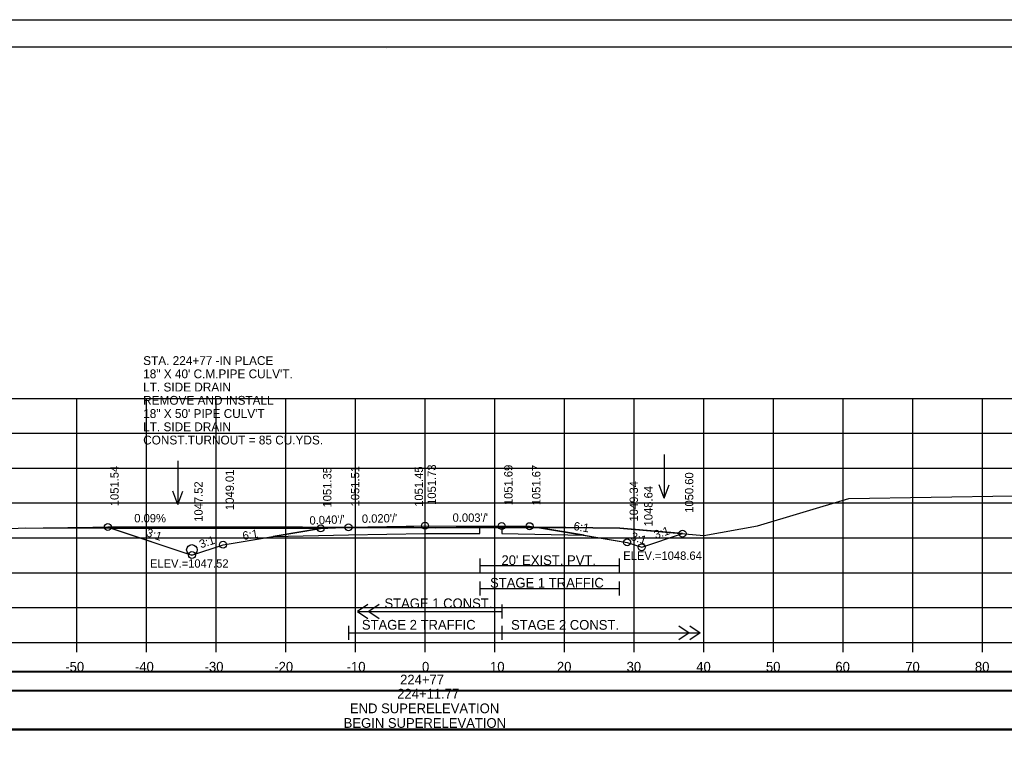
# Model space of a CAD drawing. Extents: x 1370565 to 1374448, y 301010 to 304637.
# Drawn here: x 1373310.6 to 1373451.9, y 303328.6 to 303431.7 of the extents above; entities that cross this region are included whole.
import ezdxf

# ---------------------------------------------------------------- set-up
doc = ezdxf.new("R2010")
doc.units = 0
for name, color, linetype in [('Default', 7, 'Continuous'), ('R_Alt Surface', 7, 'Continuous'), ('R_Axis', 7, 'Continuous'), ('R_Axis Annot', 7, 'Continuous'), ('R_Border', 7, 'Continuous'), ('R_Contours', 7, 'Continuous'), ('R_Drive', 7, 'Continuous'), ('R_Exist Surface', 7, 'Continuous'), ('R_Fin Surface', 7, 'Continuous'), ('R_Grid', 7, 'Continuous'), ('R_No Plot', 7, 'Continuous'), ('R_Water', 7, 'Continuous'), ('R_Water Annot', 7, 'Continuous'), ('R_Xsect Elev', 7, 'Continuous'), ('R_Xsect Slope', 7, 'Continuous')]:
    doc.layers.add(name, color=color, linetype=linetype)

msp = doc.modelspace()

# ---------------------------------------------------------------- linework, layer by layer
at = {"layer": 'Default'}
for points in [[(1373219.61, 303335.38), (1373518.02, 303335.38), (1373518.02, 303338.08), (1373219.61, 303338.08)], [(1373219.61, 303329.8), (1373518.02, 303329.8), (1373518.02, 303335.32), (1373219.61, 303335.32)]]:
    msp.add_lwpolyline(points, close=True, dxfattribs=at)
at = {"layer": 'R_Alt Surface'}
for points in [[(1373346.98, 303357.55), (1373357.81, 303357.76), (1373368.81, 303357.98), (1373376.68, 303357.95), (1373376.68, 303358.87), (1373379.81, 303358.86), (1373379.82, 303357.94), (1373379.81, 303357.94), (1373391.65, 303357.71)], [(1373360.61, 303347.76), (1373359.11, 303346.76), (1373360.61, 303345.76)], [(1373362.21, 303347.76), (1373360.71, 303346.76), (1373362.21, 303345.76)], [(1373359.11, 303346.76), (1373379.81, 303346.76)], [(1373357.81, 303344.69), (1373357.81, 303342.69)], [(1373357.81, 303343.69), (1373379.81, 303343.69)], [(1373379.81, 303344.69), (1373379.81, 303342.69)], [(1373379.81, 303344.69), (1373379.81, 303342.69)], [(1373379.81, 303343.69), (1373408.3, 303343.69)], [(1373405.21, 303344.69), (1373406.71, 303343.69), (1373405.21, 303342.69)], [(1373406.8, 303344.69), (1373408.3, 303343.69), (1373406.8, 303342.69)]]:
    msp.add_lwpolyline(points, dxfattribs=at)
at = {"layer": 'R_Axis'}
for p, q in [((1373218.81, 303342.34), (1373518.81, 303342.34)), ((1373318.81, 303340.94), (1373318.81, 303342.34)), ((1373328.81, 303340.94), (1373328.81, 303342.34)), ((1373338.81, 303340.94), (1373338.81, 303342.34)), ((1373348.81, 303340.94), (1373348.81, 303342.34)), ((1373358.81, 303340.94), (1373358.81, 303342.34)), ((1373368.81, 303340.94), (1373368.81, 303342.34)), ((1373378.81, 303340.94), (1373378.81, 303342.34)), ((1373388.81, 303340.94), (1373388.81, 303342.34)), ((1373398.81, 303340.94), (1373398.81, 303342.34)), ((1373408.81, 303340.94), (1373408.81, 303342.34)), ((1373418.81, 303340.94), (1373418.81, 303342.34)), ((1373428.81, 303340.94), (1373428.81, 303342.34)), ((1373438.81, 303340.94), (1373438.81, 303342.34)), ((1373448.81, 303340.94), (1373448.81, 303342.34))]:
    msp.add_line(p, q, dxfattribs=at)
for points in [[(1373376.68, 303354.37), (1373376.68, 303352.37)], [(1373376.68, 303353.37), (1373396.68, 303353.37)], [(1373396.68, 303354.37), (1373396.68, 303352.37)], [(1373376.68, 303351.05), (1373376.68, 303349.05)], [(1373396.68, 303351.05), (1373396.68, 303349.05)], [(1373376.68, 303350.05), (1373396.68, 303350.05)], [(1373379.81, 303347.76), (1373379.81, 303345.76)]]:
    msp.add_lwpolyline(points, dxfattribs=at)
at = {"layer": 'R_Border'}
for p, q in [((1373210.81, 303427.8), (1373526.99, 303427.8)), ((1373363.33, 303427.54), (1373363.33, 303427.54)), ((1373363.33, 303427.54), (1373363.33, 303427.54))]:
    msp.add_line(p, q, dxfattribs=at)
at = {"layer": 'R_Contours'}
for p, q in [((1373323.27, 303358.88), (1373323.76, 303358.71)), ((1373353.81, 303358.69), (1373323.76, 303358.71)), ((1373323.76, 303358.71), (1373353.81, 303358.69)), ((1373353.81, 303358.69), (1373346.98, 303357.55)), ((1373353.81, 303358.69), (1373357.02, 303358.81)), ((1373357.02, 303358.81), (1373353.81, 303358.69)), ((1373357.02, 303358.81), (1373354.24, 303358.82)), ((1373376.68, 303358.83), (1373379.81, 303358.82)), ((1373384.98, 303358.82), (1373379.81, 303358.82)), ((1373391.65, 303357.71), (1373384.98, 303358.82))]:
    msp.add_line(p, q, dxfattribs=at)
for points in [[(1373354.24, 303358.82), (1373351.22, 303358.88), (1373338.21, 303358.89), (1373336.01, 303358.86), (1373323.27, 303358.88)], [(1373323.76, 303358.71), (1373335.33, 303354.86), (1373339.81, 303356.35), (1373346.98, 303357.55), (1373353.81, 303358.69)], [(1373346.98, 303357.55), (1373357.81, 303357.76), (1373368.81, 303357.98), (1373376.68, 303357.95), (1373376.68, 303358.83)], [(1373376.68, 303358.83), (1373376.68, 303358.83), (1373373.25, 303358.83), (1373370.32, 303358.78), (1373368.81, 303358.79), (1373367.21, 303358.8), (1373357.81, 303358.81), (1373357.02, 303358.81)], [(1373379.81, 303358.86), (1373376.68, 303358.87), (1373376.68, 303358.83)], [(1373379.81, 303358.82), (1373379.81, 303358.86)], [(1373379.81, 303358.82), (1373379.82, 303357.94), (1373391.65, 303357.71)], [(1373405.76, 303357.94), (1373396.76, 303358.73), (1373389.01, 303358.8), (1373387.06, 303358.82), (1373384.98, 303358.82)], [(1373384.98, 303358.82), (1373391.65, 303357.71), (1373397.81, 303356.68)], [(1373397.81, 303356.68), (1373399.9, 303355.98), (1373405.76, 303357.94)]]:
    msp.add_lwpolyline(points, dxfattribs=at)
at = {"layer": 'R_Drive'}
msp.add_line((1373353.81, 303358.69), (1373311.47, 303358.72), dxfattribs=at)
for points in [[(1373219.61, 303335.43), (1373518.02, 303335.43), (1373518.02, 303338.14), (1373219.61, 303338.14)], [(1373219.61, 303329.91), (1373518.02, 303329.91), (1373518.02, 303335.43), (1373219.61, 303335.43)]]:
    msp.add_lwpolyline(points, close=True, dxfattribs=at)
at = {"layer": 'R_Exist Surface'}
msp.add_lwpolyline([(1373306.77, 303358.66), (1373321.12, 303358.85), (1373321.72, 303358.88), (1373336.01, 303358.86), (1373338.21, 303358.89), (1373351.22, 303358.88), (1373354.24, 303358.82), (1373367.21, 303358.8), (1373370.32, 303358.78), (1373373.25, 303358.83), (1373387.06, 303358.82), (1373389.01, 303358.8), (1373396.76, 303358.73), (1373408.82, 303357.67), (1373416.51, 303359.08), (1373429.64, 303363), (1373453.29, 303363.39), (1373492.39, 303363.87), (1373503.76, 303364.08), (1373507.58, 303364.15), (1373508.71, 303364.19), (1373518.81, 303364.44)], dxfattribs=at)
at = {"layer": 'R_Fin Surface'}
msp.add_lwpolyline([(1373323.27, 303358.88), (1373335.33, 303354.86), (1373339.81, 303356.35), (1373353.81, 303358.69), (1373357.81, 303358.85), (1373368.81, 303359.07), (1373379.81, 303359.03), (1373383.81, 303359.01), (1373397.81, 303356.68), (1373399.9, 303355.98), (1373405.76, 303357.94)], dxfattribs=at)
at = {"layer": 'R_Grid'}
for p, q in [((1373218.81, 303377.34), (1373518.81, 303377.34)), ((1373318.81, 303342.34), (1373318.81, 303377.34)), ((1373328.81, 303342.34), (1373328.81, 303377.34)), ((1373338.81, 303342.34), (1373338.81, 303377.34)), ((1373348.81, 303342.34), (1373348.81, 303377.34)), ((1373358.81, 303342.34), (1373358.81, 303377.34)), ((1373368.81, 303342.34), (1373368.81, 303377.34)), ((1373378.81, 303342.34), (1373378.81, 303377.34)), ((1373388.81, 303342.34), (1373388.81, 303377.34)), ((1373398.81, 303342.34), (1373398.81, 303377.34)), ((1373408.81, 303342.34), (1373408.81, 303377.34)), ((1373418.81, 303342.34), (1373418.81, 303377.34)), ((1373428.81, 303342.34), (1373428.81, 303377.34)), ((1373438.81, 303342.34), (1373438.81, 303377.34)), ((1373448.81, 303342.34), (1373448.81, 303377.34)), ((1373218.81, 303372.34), (1373518.81, 303372.34)), ((1373218.81, 303367.34), (1373518.81, 303367.34)), ((1373218.81, 303362.34), (1373518.81, 303362.34)), ((1373218.81, 303357.34), (1373518.81, 303357.34)), ((1373218.81, 303352.34), (1373518.81, 303352.34)), ((1373218.81, 303347.34), (1373518.81, 303347.34)), ((1373218.81, 303342.34), (1373518.81, 303342.34))]:
    msp.add_line(p, q, dxfattribs=at)
at = {"layer": 'R_No Plot'}
msp.add_line((1373198.41, 303431.69), (1373531.75, 303431.69), dxfattribs=at)
for points in [[(1373198.41, 303431.69), (1373531.75, 303431.69), (1373531.75, 303218.36), (1373198.41, 303218.36)], [(1373444.73, 303427.8), (1373464.35, 303427.8), (1373464.35, 303417.92), (1373480.47, 303417.92), (1373503.67, 303417.92), (1373503.67, 303393.59), (1373526.99, 303393.59), (1373526.99, 303222.34), (1373210.81, 303222.34), (1373210.81, 303427.8)]]:
    msp.add_lwpolyline(points, close=True, dxfattribs=at)
for centre in [(1373323.27, 303358.88), (1373353.81, 303358.69), (1373357.81, 303358.85), (1373368.81, 303359.07), (1373379.81, 303359.03), (1373383.81, 303359.01), (1373405.76, 303357.94), (1373339.81, 303356.35), (1373397.81, 303356.68), (1373399.9, 303355.98), (1373335.33, 303354.86)]:
    msp.add_circle(centre, 0.5, dxfattribs=at)
at = {"layer": 'R_Water'}
msp.add_circle((1373335.33, 303355.61), 0.75, dxfattribs=at)
at = {"layer": 'R_Water Annot'}
for p, q in [((1373403.12, 303369.32), (1373403.12, 303363.04)), ((1373333.31, 303368.41), (1373333.31, 303362.12)), ((1373403.12, 303363.04), (1373402.42, 303364.96)), ((1373403.12, 303363.04), (1373403.82, 303364.96)), ((1373333.31, 303362.12), (1373332.61, 303364.05)), ((1373333.31, 303362.12), (1373334.01, 303364.05))]:
    msp.add_line(p, q, dxfattribs=at)
at = {"layer": 'R_Xsect Elev'}
msp.add_line((1373368.81, 303358.79), (1373368.81, 303368.79), dxfattribs=at)

# ---------------------------------------------------------------- texts
at = {"layer": 'R_Axis Annot'}
for s, p in [("20' EXIST. PVT.", (1373379.77, 303353.43)), ('-50', (1373317.16, 303338.14)), ('-40', (1373327.16, 303338.14)), ('-30', (1373337.16, 303338.14)), ('-20', (1373347.16, 303338.14)), ('-10', (1373357.55, 303338.14)), ('0', (1373368.36, 303338.14)), ('10', (1373378.13, 303338.14)), ('20', (1373387.73, 303338.14)), ('30', (1373397.73, 303338.14)), ('40', (1373407.73, 303338.14)), ('50', (1373417.73, 303338.14)), ('60', (1373427.7, 303338.14)), ('70', (1373437.73, 303338.14)), ('80', (1373447.73, 303338.14)), ('224+77', (1373365.22, 303336.3)), ('224+11.77', (1373364.8, 303334.27)), ('END SUPERELEVATION', (1373358.02, 303332.17)), ('BEGIN SUPERELEVATION', (1373357.12, 303330.07))]:
    msp.add_text(s, height=1.4, dxfattribs=at).set_placement(p)
at = {"layer": 'R_Water'}
for s, p in [('STAGE 1 TRAFFIC', (1373378.13, 303350.19)), ('STAGE 1 CONST.', (1373362.97, 303347.24)), ('STAGE 2 TRAFFIC', (1373359.73, 303344.16)), ('STAGE 2 CONST.', (1373381.15, 303344.15))]:
    msp.add_text(s, height=1.4, dxfattribs=at).set_placement(p)
at = {"layer": 'R_Water Annot'}
for s, p in [('STA. 224+77 -IN PLACE ', (1373328.34, 303382.14)), ('18" X 40\' C.M.PIPE CULV\'T.', (1373328.34, 303380.24)), ('LT. SIDE DRAIN', (1373328.34, 303378.34)), ('REMOVE AND INSTALL', (1373328.34, 303376.44)), ('18" X 50\' PIPE CULV\'T', (1373328.34, 303374.54)), ('LT. SIDE DRAIN', (1373328.34, 303372.64)), ('CONST.TURNOUT = 85 CU.YDS.', (1373328.34, 303370.74))]:
    msp.add_text(s, height=1.2661, dxfattribs=at).set_placement(p)
at = {"layer": 'R_Xsect Elev'}
for s, rotation, p in [('1051.54', 90, (1373324.82, 303361.88)), ('1051.51', 90, (1373359.36, 303361.85)), ('1051.45', 90, (1373368.51, 303361.79)), ('1051.73', 90, (1373370.36, 303362.07)), ('1051.69', 90, (1373381.36, 303362.03)), ('1051.67', 90, (1373385.36, 303362.01)), ('1049.01', 90, (1373341.36, 303361.33)), ('1051.35', 90, (1373355.36, 303361.69)), ('1050.60', 90, (1373407.31, 303360.94)), ('1047.52', 90, (1373336.88, 303359.64)), ('1049.34', 90, (1373399.36, 303359.68)), ('1048.64', 90, (1373401.45, 303358.98)), ('0.09%', 359.9479, (1373327.06, 303359.56))]:
    msp.add_text(s, height=1.2, rotation=rotation, dxfattribs=at).set_placement(p)
for s, p in [('ELEV.=1048.64', (1373397.25, 303354.18)), ('ELEV.=1047.52', (1373329.31, 303353.06))]:
    msp.add_text(s, height=1.2, dxfattribs=at).set_placement(p)
at = {"layer": 'R_Xsect Slope'}
for s, rotation, p in [("0.040'/'", 2.2906, (1373352.23, 303359.22)), ("0.020'/'", 1.1458, (1373359.74, 303359.48)), ("0.003'/'", 359.8009, (1373372.75, 303359.65)), ('6:1', 350.5358, (1373390.05, 303358.48)), ('3:1', 341.5668, (1373328.67, 303357.6)), ('6:1', 9.4642, (1373342.71, 303357.02)), ('3:1', 341.5651, (1373398.23, 303357.07)), ('3:1', 18.4332, (1373401.89, 303357.17)), ('3:1', 18.4349, (1373336.63, 303355.82))]:
    msp.add_text(s, height=1.2, rotation=rotation, dxfattribs=at).set_placement(p)

doc.saveas('drawing.dxf')
